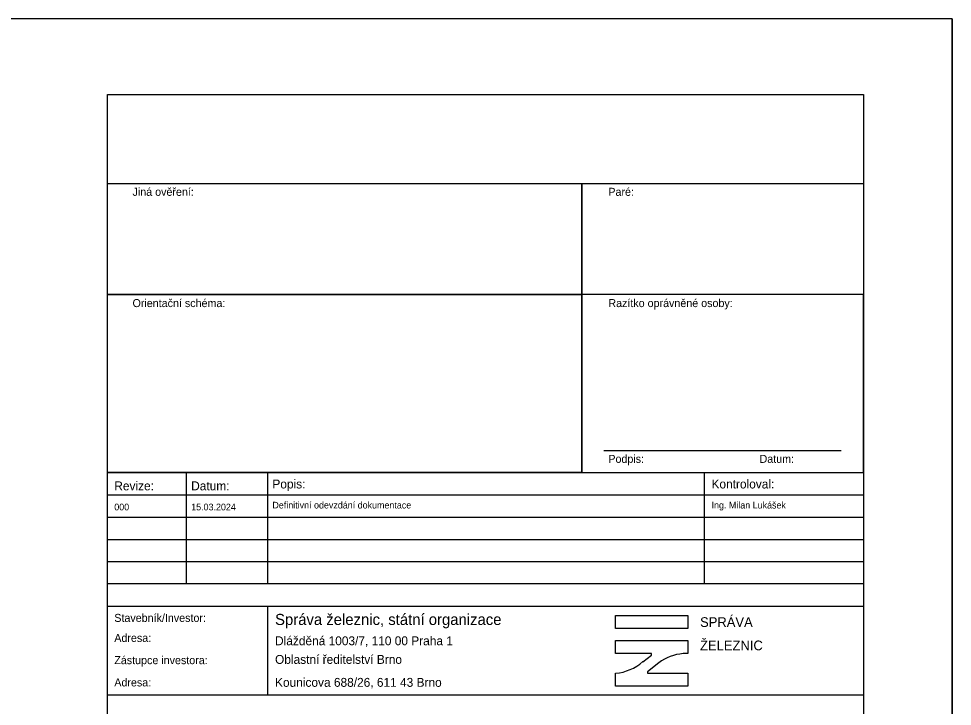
# Model space of a CAD drawing. Extents: x -193 to -151, y 303.3 to 362.7.
# Drawn here: x -172 to -151, y 347.25 to 362.7 of the extents above; entities that cross this region are included whole.
import ezdxf

# ---------------------------------------------------------------- set-up
doc = ezdxf.new("R2010")
doc.units = 0
for name, color, linetype in [('Default', 7, 'Continuous'), ('Rozpiska_Logo', 7, 'Continuous'), ('Rozpiska_pola_3', 7, 'Continuous'), ('Rozpiska_pole_1', 7, 'Continuous'), ('Rozpiska_pole_2', 7, 'Continuous'), ('Rozpiska_pole_4', 7, 'Continuous'), ('Rozpiska_pole_5', 7, 'Continuous'), ('Rozpiska_pole_6', 7, 'Continuous')]:
    doc.layers.add(name, color=color, linetype=linetype)

msp = doc.modelspace()

# ---------------------------------------------------------------- linework, layer by layer
at = {"layer": 'Default'}
for p, q in [((-151, 362.7), (-151, 333)), ((-159.335, 352.5), (-159.335, 359))]:
    msp.add_line(p, q, dxfattribs=at)
msp.add_lwpolyline([(-193, 333), (-151, 333), (-151, 362.7), (-193, 362.7)], close=True, dxfattribs=at)
at = {"layer": 'Rozpiska_Logo'}
for p, q in [((-157.96, 348.253), (-157.766, 348.399)), ((-157.766, 348.399), (-157.766, 348.434)), ((-157.597, 348.226), (-157.858, 348.024)), ((-157.858, 348.024), (-157.858, 347.993))]:
    msp.add_line(p, q, dxfattribs=at)
msp.add_lwpolyline([(-158.578, 349.291), (-156.948, 349.291), (-156.948, 348.998), (-158.578, 348.998)], close=True, dxfattribs=at)
for points in [[(-157.766, 348.434), (-158.578, 348.434), (-158.578, 348.727), (-156.948, 348.727), (-156.948, 348.434), (-157.056, 348.434)], [(-157.858, 347.993), (-156.948, 347.993), (-156.948, 347.7), (-158.578, 347.7), (-158.578, 347.993), (-158.572, 347.993)]]:
    msp.add_lwpolyline(points, dxfattribs=at)
for centre, radius, start, end in [((-156.982, 347.432), 1.004, 94.2142, 127.7808), ((-158.656, 349.042), 1.052, 274.6014, 311.4254)]:
    msp.add_arc(centre, radius, start, end, dxfattribs=at)
at = {"layer": 'Rozpiska_pola_3'}
msp.add_line((-158.835, 353), (-153.5, 353), dxfattribs=at)
at = {"layer": 'Rozpiska_pole_1'}
msp.add_lwpolyline([(-170, 361), (-153, 361), (-153, 334.5), (-170, 334.5)], close=True, dxfattribs=at)
at = {"layer": 'Rozpiska_pole_2'}
for points in [[(-170, 359), (-159.335, 359), (-159.335, 356.5), (-170, 356.5)], [(-159.335, 359), (-153, 359), (-153, 356.5), (-159.335, 356.5)], [(-170, 356.5), (-159.335, 356.5), (-159.335, 352.5), (-170, 352.5)], [(-153, 356.5), (-159.335, 356.5), (-159.335, 352.5), (-153, 352.5)]]:
    msp.add_lwpolyline(points, close=True, dxfattribs=at)
at = {"layer": 'Rozpiska_pole_4'}
for p, q in [((-168.223, 350), (-168.223, 352.5)), ((-166.395, 350), (-166.395, 352.5)), ((-156.57, 350), (-156.57, 352.5)), ((-170, 352), (-153, 352)), ((-170, 351.5), (-153, 351.5)), ((-170, 351), (-153, 351)), ((-170, 350.5), (-153, 350.5))]:
    msp.add_line(p, q, dxfattribs=at)
msp.add_lwpolyline([(-170, 352.5), (-153, 352.5), (-153, 350), (-170, 350)], close=True, dxfattribs=at)
at = {"layer": 'Rozpiska_pole_5'}
msp.add_line((-166.395, 347.5), (-166.395, 349.5), dxfattribs=at)
msp.add_lwpolyline([(-170, 349.5), (-153, 349.5), (-153, 347.5), (-170, 347.5)], close=True, dxfattribs=at)

# ---------------------------------------------------------------- texts
at = {"layer": 'Rozpiska_pola_3'}
for s, p in [('Paré:', (-158.735, 358.72)), ('Razítko oprávněné osoby:', (-158.735, 356.22)), ('Podpis:', (-158.735, 352.72)), ('Datum:', (-155.335, 352.72))]:
    msp.add_text(s, height=0.18, dxfattribs=at).set_placement(p)
at = {"layer": 'Rozpiska_pole_2'}
for s, p in [('Jiná ověření:', (-169.435, 358.72)), ('Orientační schéma:', (-169.435, 356.22))]:
    msp.add_text(s, height=0.18, dxfattribs=at).set_placement(p)
at = {"layer": 'Rozpiska_pole_4'}
for s, height, p in [('Revize:', 0.2, (-169.845, 352.103)), ('Popis:', 0.2, (-166.29, 352.145)), ('Kontroloval:', 0.2, (-156.415, 352.145)), ('Datum:', 0.2, (-168.116, 352.103)), ('000', 0.15, (-169.845, 351.653)), ('15.03.2024', 0.15, (-168.116, 351.653)), ('Definitivní odevzdání dokumentace', 0.15, (-166.29, 351.695)), ('Ing. Milan Lukášek', 0.15, (-156.415, 351.695))]:
    msp.add_text(s, height=height, dxfattribs=at).set_placement(p)
at = {"layer": 'Rozpiska_pole_5'}
for s, height, p in [('Stavebník/Investor:', 0.18, (-169.845, 349.147)), ('Správa železnic, státní organizace', 0.25, (-166.23, 349.077)), ('Adresa:', 0.18, (-169.845, 348.697)), ('Zástupce investora:', 0.18, (-169.845, 348.197)), ('Adresa:', 0.18, (-169.845, 347.697))]:
    msp.add_text(s, height=height, dxfattribs=at).set_placement(p)
at = {"layer": 'Rozpiska_pole_6'}
for s, height, p in [('SPRÁVA', 0.2183, (-156.673, 349.033)), ('Dlážděná 1003/7, 110 00 Praha 1', 0.2, (-166.23, 348.622)), ('ŽELEZNIC', 0.2183, (-156.673, 348.509)), ('Oblastní ředitelství Brno', 0.2, (-166.23, 348.204)), ('Kounicova 688/26, 611 43 Brno', 0.2, (-166.23, 347.688))]:
    msp.add_text(s, height=height, dxfattribs=at).set_placement(p)

doc.saveas('drawing.dxf')
